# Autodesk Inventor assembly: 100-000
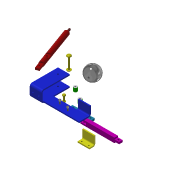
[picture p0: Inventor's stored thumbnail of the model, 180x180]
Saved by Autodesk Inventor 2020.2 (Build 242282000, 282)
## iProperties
Created: 2014-01
Part Number: 100-000
Document SubType Name: Assembly
Designer: F.Stasiak
Manager: www.cadconsulting.pl
Company: Fabian Stasiak CAD Consulting
Author: F.Stasiak
Subject: Zbiór ćwiczeń. Autodesk Inventor 2020. Kurs podstawowy
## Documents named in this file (11)
- C:\2020_Kurs_podstawowy\R6 Zespoły\Warsztat\100-000.iam
- C:\2020_Kurs_podstawowy\R6 Zespoły\Warsztat\Komponenty\100-002.ipt
- C:\2020_Kurs_podstawowy\R6 Zespoły\Warsztat\Komponenty\100-003.ipt
- C:\2020_Kurs_podstawowy\R6 Zespoły\Warsztat\Komponenty\100-004.ipt
- C:\2020_Kurs_podstawowy\R6 Zespoły\Warsztat\Komponenty\100-005.ipt
- C:\2020_Kurs_podstawowy\R6 Zespoły\Warsztat\Komponenty\100-006.ipt
- C:\2020_Kurs_podstawowy\R6 Zespoły\Warsztat\Komponenty\100-007.ipt
- C:\2020_Kurs_podstawowy\R6 Zespoły\Warsztat\Komponenty\100-008.ipt
- C:\2020_Kurs_podstawowy\R6 Zespoły\Warsztat\Komponenty\100-009.ipt
- C:\2020_Kurs_podstawowy\Zasoby\Content Center Files\pl-PL\ISO 4762(2)\ISO 4762 - M5 x 12ISO.ipt
- C:\2020_Kurs_podstawowy\R6 Zespoły\Warsztat\Komponenty\100-001.ipt
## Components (13 placed, 10 different names)
1. 100-001:1
2. 100-002:1
3. 100-003:1
4. 100-003:2
5. 100-004:1
6. 100-005:1
7. 100-006:1
8. 100-007:1
9. 100-008:1
10. 100-009:1
11. 100-009:2
12. ISO 4762 M5 x 12:1
13. ISO 4762 M5 x 12:2
